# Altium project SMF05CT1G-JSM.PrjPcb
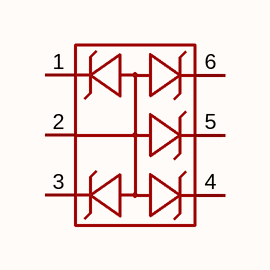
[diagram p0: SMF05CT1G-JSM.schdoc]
1 sheet, 1 parts. Net scope: global (net labels, ports and power ports of the same name join across sheets).

## Sheet SMF05CT1G-JSM.schdoc
size 127 x 101 mm

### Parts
D?  smf05ct1g-jsm  [SOT-363_L2.0-W1.3-P0.65-LS2.1-BL]  (value not drawn)

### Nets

Not connected (* = marked no-connect by the designer): D? 1 2 3 4 5 6

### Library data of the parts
D? = smf05ct1g-jsm: 极性:单向;反向截止电压(Vrwm):5V;钳位电压:18V;峰值脉冲电流(Ipp):6A@8/20us;峰值脉冲功率(Ppp):100W@8/20us;击穿电压(VBR):8V;; Manufacturer: JSMSEMI(杰盛微); AddInBom: yes; ModelId: ea15c7b026c54341854a7f0d9614aed9; ModelName: SOT-363-6P_L2.0-W1.3-H1.1-LS2.0-P0.65; ModelTransform: 83.17133,78.74,0,90,0,0,0,0,0; Polarity: 单向; Reverse Stand-Off Voltage (Vrwm): 5V; Clamping Voltage: 18V; Voltage - Breakdown: 8V; Reverse Leakage Current (Ir): 5uA; Number of Channels: 五路; level of protection: IEC 61000-4-2; Type: ESD; Junction Capacitance: 50pF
